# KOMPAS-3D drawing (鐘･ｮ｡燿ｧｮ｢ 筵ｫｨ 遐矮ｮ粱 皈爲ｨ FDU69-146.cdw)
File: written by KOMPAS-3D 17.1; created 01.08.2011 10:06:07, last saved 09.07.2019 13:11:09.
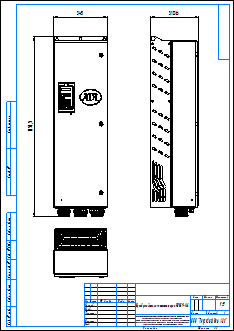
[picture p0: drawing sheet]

Title block, sheet 1: name: Преобразователи частоты серии FDU69-146; scale: 1:5; sheets: 1; sheet format: A3; stored path: \\adlc.lan\data\АДЛ_ПКД\3D-модели\Поставщики\Оборудование Emotron\Преобразователи частоты\Серия FDU 2.0\KOMPAS 2D\Преобразователи частоты серии FDU69-146.cdw

Views: Спереди 1
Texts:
  Рама для чертежей
  Лит-Масса-Масштаб
  Материал-Предприятие
  Масштаб
  Изм.
  Лист
  № докум.
  Подп.
  Дата
  Лит.
  Разраб.
  Пров.
  Т.контр.
  Листов
  Внимание! Данный продукт является объектом авторского права ООО «Торговый Дом АДЛ».
  Запрещается изменение, копирование, распространение
  (в том числе путем копирования на другие сайты и ресурсы в Интернете)
  или любое иное использование информации и объектов без предварительного
  согласия правообладателя (ООО «Торговый Дом АДЛ»).
  Н.контр.
  Утв.
  ООО "Торговый дом АДЛ"
  Изменение
  Номер документа
  Подпись
  Обозначение документа
  Наименование изделия
  Масса изделия по ГОСТ 2.109-73
  Порядковый номер листа
  Общее количество листов в документе
  Характер работы, выполненной лицом, подписавшим документ
  Наименование или индекс предприятия, выпускающего документ
  Инв. № подл.
  Подп. и дата
  Взам. инв. №
  Инв. № дубл.
  Инвентарный номер подлинника по ГОСТ 2.501-68
  Подпись принявшего подлинник в отдел технической документации
  Инвентарный номер подлинника, взамен которого выпущен данный подлинник
  Инвентарный номер дубликата по ГОСТ 2.502-68
  Подпись принявшего дубликат в отдел технической документации
  Справ. №
  Перв. примен.
  Обозначение документа, взамен или на основании которого выпущен данный документ
  Обозначение документа, в котором впервые записан данный документ
  Подпись лица, копировавшего чертеж
  Обозначение формата листа
  !Рама для чертежа
Dimensions and other numbers on the sheet: 1151,5; 345; 310,6; 1:5; 1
